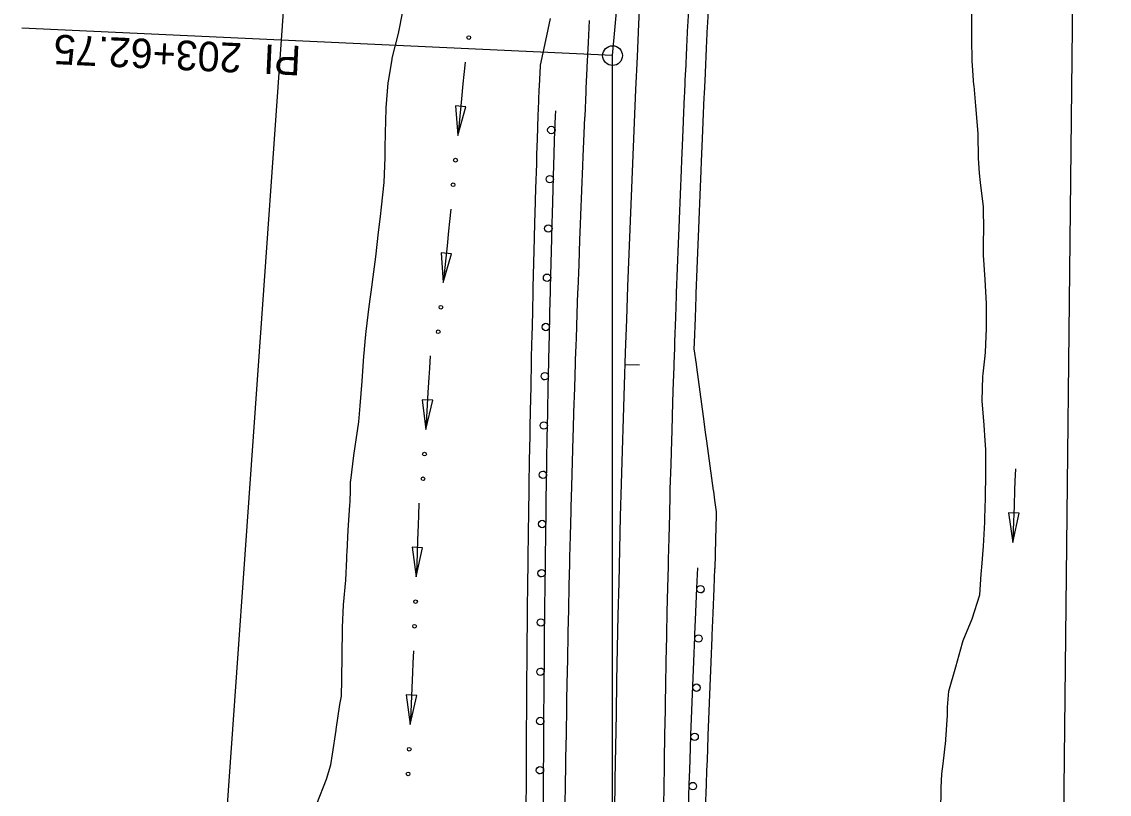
# Model space of a CAD drawing. Extents: x 1 to 1477871, y 1 to 1872901.
# Drawn here: x 1438491.3 to 1438712, y 1870149.1 to 1870306 of the extents above; entities that cross this region are included whole.
import ezdxf

# ---------------------------------------------------------------- set-up
doc = ezdxf.new("R2010")
doc.units = 0
for name, color, linetype in [('R_Horz Alg', 7, 'Continuous'), ('R_Horz Alg Annot', 7, 'Continuous'), ('R_Proposed Const Limits_Cut', 7, 'Continuous'), ('R_Proposed Road_Lane', 7, 'Continuous'), ('R_Proposed Road_Shoulder', 7, 'Continuous'), ('R_ROW', 7, 'Continuous'), ('R_Steel', 7, 'Continuous'), ('R_Water', 7, 'Continuous')]:
    doc.layers.add(name, color=color, linetype=linetype)

msp = doc.modelspace()

# ---------------------------------------------------------------- linework, layer by layer
at = {"layer": 'R_Horz Alg'}
msp.add_arc((1443194.86, 1870085.35), 4583.66, 174.66013, 180, dxfattribs=at)
at = {"layer": 'R_Horz Alg Annot'}
for p, q in [((1438611.19, 1870299.1), (1438631.09, 1870511.92)), ((1438611.19, 1870085.35), (1438611.19, 1870299.1))]:
    msp.add_line(p, q, dxfattribs=at)
for points in [[(1438611.19, 1870299.1), (1438491.32, 1870304.69)], [(1438616.68, 1870236.23), (1438613.68, 1870236.33)]]:
    msp.add_lwpolyline(points, dxfattribs=at)
msp.add_circle((1438611.19, 1870299.1), 2, dxfattribs=at)
at = {"layer": 'R_Proposed Const Limits_Cut'}
for points in [[(1438551.17, 1870147.16), (1438553.16, 1870152.19), (1438554.07, 1870155.12), (1438554.38, 1870157.24), (1438555.1, 1870162.11), (1438555.13, 1870162.29), (1438555.89, 1870167.34), (1438556.18, 1870169.04), (1438556.26, 1870172.39), (1438556.31, 1870177.45), (1438556.37, 1870182.52), (1438556.38, 1870182.98), (1438556.64, 1870187.57), (1438557.08, 1870192.62), (1438557.25, 1870196.91), (1438557.29, 1870197.68), (1438557.32, 1870198.37), (1438557.55, 1870202.74), (1438557.9, 1870207.79), (1438557.93, 1870208.48), (1438558.02, 1870210.84), (1438558.06, 1870212.66), (1438558.07, 1870212.84), (1438558.67, 1870217.89), (1438559.48, 1870222.93), (1438559.72, 1870224.75), (1438559.98, 1870227.97), (1438560.38, 1870233.02), (1438560.76, 1870238.07), (1438560.81, 1870238.66), (1438561.07, 1870241.78), (1438561.2, 1870243.11), (1438561.83, 1870248.15), (1438562.41, 1870252.55), (1438562.49, 1870253.19), (1438563.16, 1870258.23), (1438563.72, 1870263.26), (1438564.08, 1870266.43), (1438564.29, 1870268.3), (1438564.85, 1870273.34), (1438565.06, 1870278.39), (1438565.09, 1870280.33), (1438565.15, 1870283.44), (1438565.24, 1870288.32), (1438565.25, 1870288.5), (1438565.7, 1870293.54), (1438565.81, 1870294.25), (1438566.46, 1870298.38), (1438566.5, 1870298.56), (1438567.78, 1870303.56), (1438568.62, 1870308.06)], [(1438677.81, 1870145.47), (1438677.89, 1870150.4), (1438678.03, 1870153.26), (1438678.27, 1870155.32), (1438678.83, 1870160.06), (1438678.85, 1870160.24), (1438679.15, 1870165.16), (1438679.16, 1870166.82), (1438679.42, 1870170.08), (1438680.83, 1870174.98), (1438682.23, 1870179.88), (1438682.36, 1870180.33), (1438684.16, 1870184.76), (1438685.69, 1870189.65), (1438686, 1870193.82), (1438686.05, 1870194.56), (1438686.1, 1870195.23), (1438686.43, 1870199.47), (1438686.74, 1870204.39), (1438686.76, 1870205.05), (1438686.81, 1870207.36), (1438686.86, 1870209.13), (1438686.86, 1870209.3), (1438686.94, 1870214.22), (1438686.93, 1870219.15), (1438686.8, 1870220.92), (1438686.57, 1870224.08), (1438686.22, 1870229.01), (1438686.3, 1870233.93), (1438686.37, 1870234.5), (1438686.72, 1870237.54), (1438686.87, 1870238.84), (1438687.06, 1870243.75), (1438687.08, 1870248.05), (1438687.08, 1870248.68), (1438686.79, 1870253.61), (1438686.48, 1870258.55), (1438686.48, 1870261.64), (1438686.5, 1870263.47), (1438686.45, 1870268.4), (1438685.88, 1870273.35), (1438685.66, 1870275.26), (1438685.42, 1870278.3), (1438685.4, 1870283.05), (1438685.39, 1870283.23), (1438684.96, 1870288.17), (1438684.9, 1870288.87), (1438684.54, 1870292.95), (1438684.53, 1870293.12), (1438684.18, 1870298.07), (1438684.12, 1870302.5), (1438684.12, 1870303.01), (1438684.12, 1870307.94)]]:
    msp.add_lwpolyline(points, dxfattribs=at)
at = {"layer": 'R_Proposed Road_Lane'}
for points in [[(1438621.6, 1870146.22), (1438621.67, 1870151.21), (1438621.71, 1870154.1), (1438621.74, 1870156.2), (1438621.82, 1870161), (1438621.82, 1870161.18), (1438621.91, 1870166.17), (1438621.94, 1870167.85), (1438622, 1870171.16), (1438622.09, 1870176.15), (1438622.2, 1870181.14), (1438622.21, 1870181.6), (1438622.3, 1870186.12), (1438622.42, 1870191.11), (1438622.52, 1870195.34), (1438622.53, 1870196.1), (1438622.55, 1870196.78), (1438622.66, 1870201.09), (1438622.79, 1870206.07), (1438622.8, 1870206.75), (1438622.87, 1870209.09), (1438622.92, 1870210.88), (1438622.92, 1870211.06), (1438623.06, 1870216.05), (1438623.21, 1870221.04), (1438623.26, 1870222.83), (1438623.36, 1870226.02), (1438623.51, 1870231.01), (1438623.68, 1870236), (1438623.69, 1870236.58), (1438623.8, 1870239.67), (1438623.84, 1870240.98), (1438624.02, 1870245.97), (1438624.17, 1870250.32), (1438624.19, 1870250.95), (1438624.38, 1870255.94), (1438624.56, 1870260.93), (1438624.69, 1870264.06), (1438624.76, 1870265.91), (1438624.96, 1870270.9), (1438625.16, 1870275.88), (1438625.24, 1870277.8), (1438625.37, 1870280.86), (1438625.58, 1870285.67), (1438625.59, 1870285.85), (1438625.81, 1870290.83), (1438625.84, 1870291.54), (1438626.03, 1870295.64), (1438626.04, 1870295.82), (1438626.27, 1870300.8), (1438626.48, 1870305.27), (1438626.51, 1870305.79), (1438626.75, 1870310.77)], [(1438601.6, 1870146.48), (1438601.67, 1870151.49), (1438601.71, 1870154.4), (1438601.75, 1870156.51), (1438601.82, 1870161.33), (1438601.82, 1870161.52), (1438601.91, 1870166.53), (1438601.94, 1870168.21), (1438602, 1870171.54), (1438602.1, 1870176.54), (1438602.2, 1870181.55), (1438602.21, 1870182.02), (1438602.31, 1870186.56), (1438602.42, 1870191.57), (1438602.52, 1870195.82), (1438602.54, 1870196.58), (1438602.56, 1870197.27), (1438602.67, 1870201.59), (1438602.79, 1870206.6), (1438602.81, 1870207.28), (1438602.88, 1870209.63), (1438602.92, 1870211.43), (1438602.93, 1870211.61), (1438603.07, 1870216.62), (1438603.22, 1870221.63), (1438603.27, 1870223.44), (1438603.37, 1870226.64), (1438603.52, 1870231.65), (1438603.69, 1870236.66), (1438603.71, 1870237.24), (1438603.81, 1870240.34), (1438603.85, 1870241.66), (1438604.03, 1870246.67), (1438604.18, 1870251.04), (1438604.21, 1870251.68), (1438604.39, 1870256.69), (1438604.58, 1870261.69), (1438604.7, 1870264.84), (1438604.78, 1870266.7), (1438604.98, 1870271.71), (1438605.18, 1870276.71), (1438605.26, 1870278.64), (1438605.39, 1870281.72), (1438605.6, 1870286.55), (1438605.61, 1870286.73), (1438605.83, 1870291.73), (1438605.86, 1870292.44), (1438606.05, 1870296.56), (1438606.06, 1870296.74), (1438606.29, 1870301.74), (1438606.51, 1870306.23)]]:
    msp.add_lwpolyline(points, dxfattribs=at)
at = {"layer": 'R_Proposed Road_Shoulder'}
for points in [[(1438632.01, 1870194.97), (1438632.16, 1870200.85), (1438632.28, 1870205.82), (1438632.3, 1870206.5), (1438631.97, 1870208.84), (1438631.72, 1870210.64), (1438631.7, 1870210.82), (1438631.01, 1870215.82), (1438630.32, 1870220.82), (1438630.07, 1870222.63), (1438629.64, 1870225.83), (1438628.96, 1870230.84), (1438628.29, 1870235.84), (1438628.21, 1870236.43), (1438627.79, 1870239.53), (1438627.84, 1870240.85), (1438628.01, 1870245.83), (1438628.17, 1870250.18), (1438628.19, 1870250.81), (1438628.37, 1870255.79), (1438628.56, 1870260.77), (1438628.68, 1870263.9), (1438628.76, 1870265.75), (1438628.96, 1870270.73), (1438629.16, 1870275.71), (1438629.24, 1870277.63), (1438629.37, 1870280.69), (1438629.58, 1870285.5), (1438629.59, 1870285.68), (1438629.81, 1870290.65), (1438629.84, 1870291.36), (1438630.03, 1870295.46), (1438630.03, 1870295.63), (1438630.27, 1870300.61), (1438630.48, 1870305.08), (1438630.5, 1870305.59), (1438630.75, 1870310.57)], [(1438596.16, 1870288.06), (1438596.34, 1870292.16), (1438596.37, 1870292.87), (1438596.56, 1870297), (1438596.6, 1870297.17), (1438597.67, 1870302.15), (1438598.63, 1870306.61)], [(1438593.7, 1870146.59), (1438593.71, 1870151.61), (1438593.72, 1870154.52), (1438593.73, 1870156.63), (1438593.75, 1870161.47), (1438593.75, 1870161.65), (1438593.78, 1870166.67), (1438593.79, 1870168.36), (1438593.82, 1870171.69), (1438593.86, 1870176.71), (1438593.9, 1870181.73), (1438593.91, 1870182.19), (1438593.95, 1870186.75), (1438594.01, 1870191.77), (1438594.06, 1870196.03), (1438594.07, 1870196.79), (1438594.08, 1870197.47), (1438594.14, 1870201.81), (1438594.21, 1870206.83), (1438594.22, 1870207.51), (1438594.26, 1870209.86), (1438594.28, 1870211.67), (1438594.29, 1870211.85), (1438594.37, 1870216.87), (1438594.46, 1870221.89), (1438594.49, 1870223.7), (1438594.55, 1870226.91), (1438594.66, 1870231.93), (1438594.76, 1870236.95), (1438594.77, 1870237.54), (1438594.84, 1870240.64), (1438594.87, 1870241.97), (1438594.99, 1870246.99), (1438595.09, 1870251.37), (1438595.11, 1870252.01), (1438595.24, 1870257.03), (1438595.37, 1870262.05), (1438595.46, 1870265.2), (1438595.51, 1870267.07), (1438595.65, 1870272.09), (1438595.8, 1870277.1), (1438595.86, 1870279.04), (1438595.96, 1870282.12), (1438596.11, 1870286.96), (1438596.12, 1870287.14), (1438596.16, 1870288.06)], [(1438630.08, 1870146.1), (1438630.25, 1870151.08), (1438630.35, 1870153.97), (1438630.43, 1870156.06), (1438630.6, 1870160.86), (1438630.61, 1870161.04), (1438630.79, 1870166.02), (1438630.86, 1870167.69), (1438630.98, 1870170.99), (1438631.18, 1870175.97), (1438631.38, 1870180.94), (1438631.4, 1870181.4), (1438631.59, 1870185.92), (1438631.8, 1870190.9), (1438631.98, 1870194.97)]]:
    msp.add_lwpolyline(points, dxfattribs=at)
at = {"layer": 'R_ROW'}
for p, q in [((1438531.34, 1870121.98), (1438591.99, 1870985.89)), ((1438711.98, 1870984.32), (1438701.19, 1870006.35))]:
    msp.add_line(p, q, dxfattribs=at)
at = {"layer": 'R_Steel'}
for points in [[(1438597.2, 1870146.58), (1438597.21, 1870151.6), (1438597.22, 1870154.51), (1438597.23, 1870156.61), (1438597.25, 1870161.45), (1438597.25, 1870161.63), (1438597.28, 1870166.65), (1438597.29, 1870168.33), (1438597.32, 1870171.66), (1438597.36, 1870176.68), (1438597.4, 1870181.7), (1438597.4, 1870182.16), (1438597.45, 1870186.71), (1438597.51, 1870191.73), (1438597.56, 1870195.98), (1438597.57, 1870196.75), (1438597.58, 1870197.43), (1438597.64, 1870201.76), (1438597.71, 1870206.78), (1438597.72, 1870207.46), (1438597.76, 1870209.81), (1438597.78, 1870211.61), (1438597.79, 1870211.79), (1438597.87, 1870216.81), (1438597.96, 1870221.83), (1438597.99, 1870223.63), (1438598.05, 1870226.84), (1438598.15, 1870231.86), (1438598.26, 1870236.87), (1438598.34, 1870240.57), (1438598.37, 1870241.89), (1438598.49, 1870246.9), (1438598.59, 1870251.28), (1438598.61, 1870251.92), (1438598.74, 1870256.94), (1438598.87, 1870261.95), (1438598.95, 1870265.11), (1438599.01, 1870266.97), (1438599.15, 1870271.98), (1438599.3, 1870277), (1438599.36, 1870278.93), (1438599.45, 1870282.01), (1438599.61, 1870286.83), (1438599.66, 1870287.91)], [(1438626.59, 1870146.22), (1438626.76, 1870151.2), (1438626.86, 1870154.09), (1438626.93, 1870156.18), (1438627.1, 1870160.99), (1438627.11, 1870161.17), (1438627.3, 1870166.15), (1438627.36, 1870167.82), (1438627.49, 1870171.13), (1438627.68, 1870176.11), (1438627.88, 1870181.09), (1438627.9, 1870181.55), (1438628.09, 1870186.07), (1438628.3, 1870191.05), (1438628.48, 1870195.12)]]:
    msp.add_lwpolyline(points, dxfattribs=at)
for centre, major_axis in [((1438598.78, 1870283.99), (-0.528, -0.532)), ((1438598.46, 1870274), (-0.528, -0.532)), ((1438598.17, 1870264), (-0.527, -0.533)), ((1438597.91, 1870254), (-0.526, -0.535)), ((1438597.67, 1870244), (-0.525, -0.536)), ((1438597.45, 1870234), (-0.524, -0.536)), ((1438597.25, 1870224), (-0.523, -0.537)), ((1438597.07, 1870214), (-0.522, -0.539)), ((1438596.91, 1870204), (-0.521, -0.539)), ((1438596.79, 1870194), (-0.519, -0.542)), ((1438629.04, 1870190.75), (-0.535, -0.525)), ((1438596.67, 1870184), (-0.518, -0.542)), ((1438628.62, 1870180.76), (-0.534, -0.527)), ((1438596.58, 1870174), (-0.517, -0.543)), ((1438628.22, 1870170.77), (-0.533, -0.527)), ((1438596.52, 1870164), (-0.516, -0.544)), ((1438627.85, 1870160.78), (-0.532, -0.529)), ((1438596.47, 1870154), (-0.515, -0.545)), ((1438627.49, 1870150.79), (-0.531, -0.53))]:
    msp.add_ellipse(centre, major_axis=major_axis, ratio=0.998743, dxfattribs=at)
at = {"layer": 'R_Water'}
for p, q in [((1438581.45, 1870288.72), (1438579.34, 1870288.93)), ((1438579.34, 1870288.93), (1438579.8, 1870282.85)), ((1438579.8, 1870282.85), (1438581.45, 1870288.72)), ((1438578.51, 1870258.86), (1438576.41, 1870259.07)), ((1438576.41, 1870259.07), (1438576.84, 1870253)), ((1438576.84, 1870253), (1438578.51, 1870258.86)), ((1438574.71, 1870229.11), (1438572.59, 1870229.23)), ((1438572.59, 1870229.23), (1438573.3, 1870223.18)), ((1438573.3, 1870223.18), (1438574.71, 1870229.11)), ((1438693.67, 1870206.2), (1438691.56, 1870206.28)), ((1438691.56, 1870206.28), (1438692.39, 1870200.24)), ((1438692.39, 1870200.24), (1438693.67, 1870206.2)), ((1438572.65, 1870199.19), (1438570.54, 1870199.27)), ((1438570.54, 1870199.27), (1438571.38, 1870193.24)), ((1438571.38, 1870193.24), (1438572.65, 1870199.19)), ((1438571.46, 1870169.21), (1438569.34, 1870169.31)), ((1438569.34, 1870169.31), (1438570.13, 1870163.27)), ((1438570.13, 1870163.27), (1438571.46, 1870169.21))]:
    msp.add_line(p, q, dxfattribs=at)
for points in [[(1438581.28, 1870297.78), (1438581.04, 1870295.27), (1438580.85, 1870293.4), (1438580.54, 1870290.31), (1438580.05, 1870285.35), (1438579.8, 1870282.85)], [(1438578.38, 1870267.92), (1438578.12, 1870265.41), (1438577.93, 1870263.54), (1438577.61, 1870260.46), (1438577.1, 1870255.5), (1438576.84, 1870253)], [(1438574.17, 1870238.16), (1438574.03, 1870235.64), (1438573.92, 1870233.76), (1438573.74, 1870230.67), (1438573.45, 1870225.69), (1438573.3, 1870223.18)], [(1438692.94, 1870215.23), (1438692.85, 1870212.72), (1438692.78, 1870210.84), (1438692.67, 1870207.74), (1438692.49, 1870202.76), (1438692.39, 1870200.24)], [(1438571.91, 1870208.23), (1438571.82, 1870205.71), (1438571.76, 1870203.83), (1438571.65, 1870200.73), (1438571.47, 1870195.75), (1438571.38, 1870193.24)], [(1438570.8, 1870178.25), (1438570.69, 1870175.73), (1438570.61, 1870173.85), (1438570.47, 1870170.76), (1438570.24, 1870165.78), (1438570.13, 1870163.27)]]:
    msp.add_lwpolyline(points, dxfattribs=at)
for centre in [(1438582.01, 1870302.76), (1438579.33, 1870277.87), (1438578.83, 1870272.88), (1438576.36, 1870248.01), (1438575.84, 1870243.03), (1438573.04, 1870218.18), (1438572.74, 1870213.18), (1438571.23, 1870188.23), (1438571.04, 1870183.23), (1438569.94, 1870158.26), (1438569.71, 1870153.26)]:
    msp.add_circle(centre, 0.375, dxfattribs=at)

# ---------------------------------------------------------------- texts
at = {"layer": 'R_Horz Alg Annot'}
msp.add_text('PI  203+62.75', height=6, rotation=177.3301, dxfattribs=at).set_placement((1438548.1, 1870301.04))

doc.saveas('drawing.dxf')
